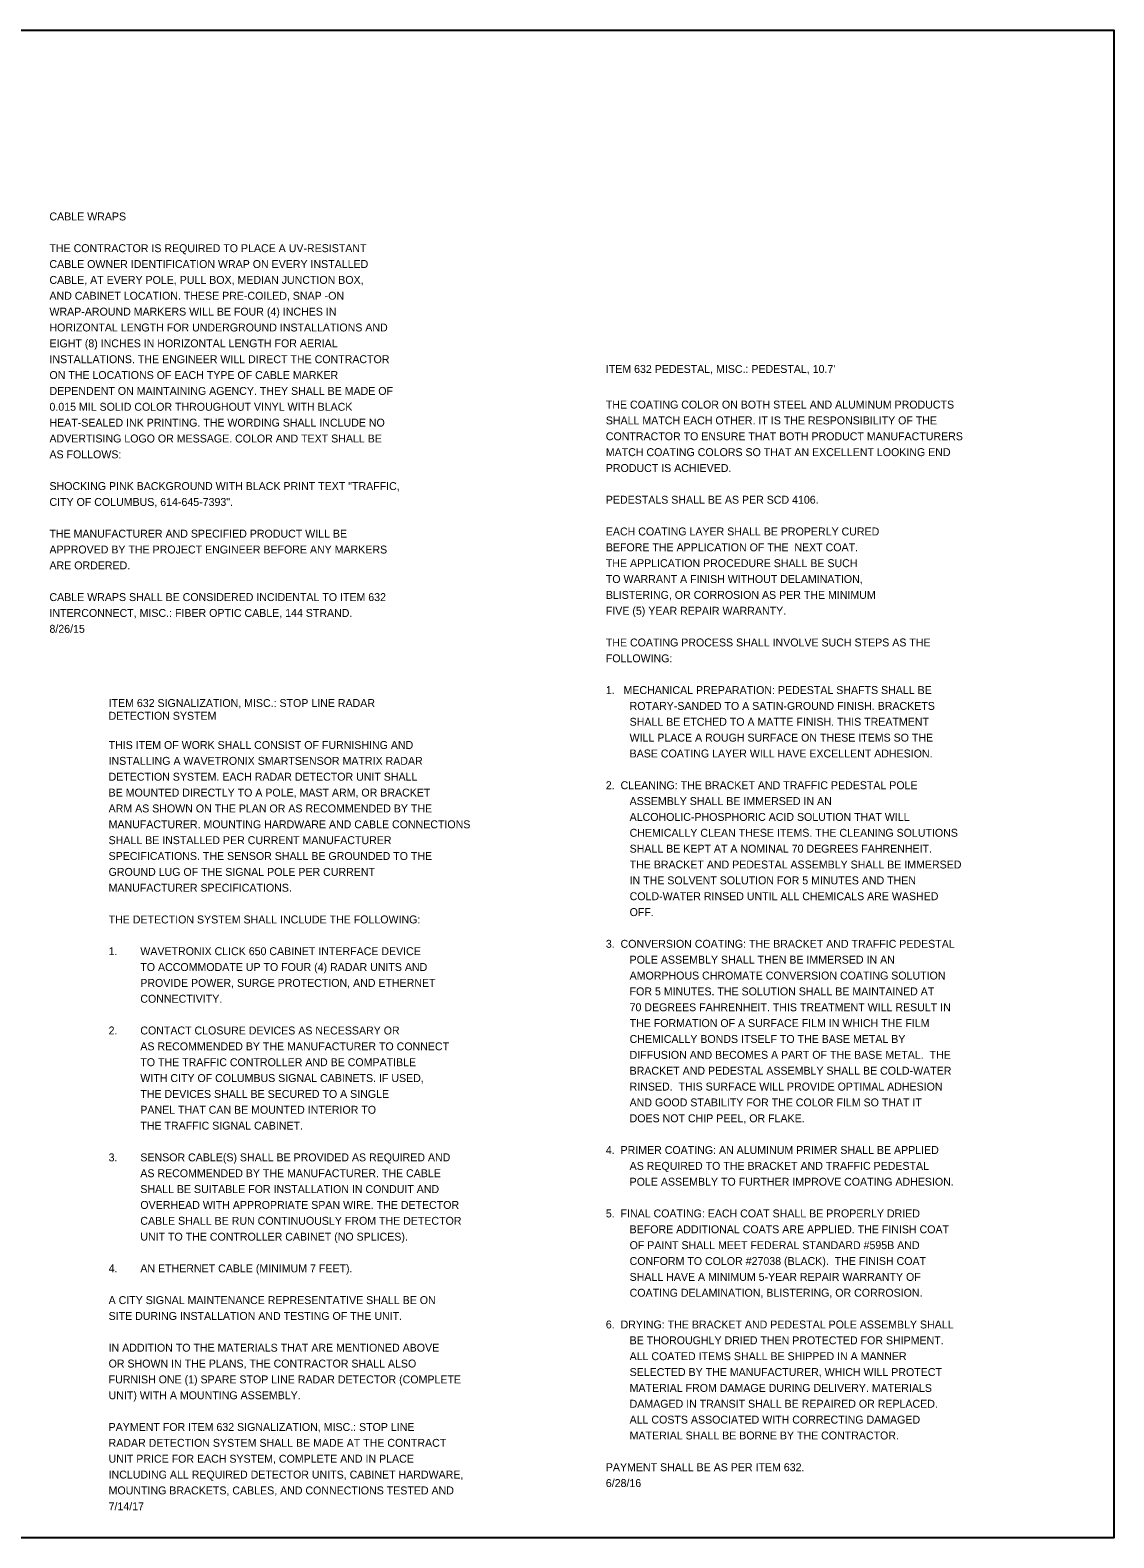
# Model space of a CAD drawing. Extents: x -41.3 to 53.7, y -40.1 to 14.5.
# Drawn here: x 12.93 to 32.05, y -40.09 to -13.47 of the extents above; entities that cross this region are included whole.
import ezdxf

# ---------------------------------------------------------------- set-up
doc = ezdxf.new("R2010")
doc.units = 0
doc.layers.add('SH_Data', color=7, linetype='Continuous')
doc.layers.add('SH_Text', color=7, linetype='Continuous')

msp = doc.modelspace()

# ---------------------------------------------------------------- linework, layer by layer
at = {"layer": 'SH_Text'}
msp.add_lwpolyline([(-41.349, -13.474), (32.055, -13.474), (32.055, -40.091), (-41.349, -40.091)], close=True, dxfattribs=at)

# ---------------------------------------------------------------- texts
at = {"layer": 'SH_Data'}
msp.add_text('CABLE WRAPS', height=0.14, dxfattribs=at).set_placement((13.266, -16.833))
for s, p in [("ITEM 632 PEDESTAL, MISC.: PEDESTAL, 10.7'", (23.087, -19.525)), ('ITEM 632 SIGNALIZATION, MISC.: STOP LINE RADAR ', (14.31, -25.423)), ('DETECTION SYSTEM', (14.31, -25.648))]:
    msp.add_text(s, height=0.14, rotation=360, dxfattribs=at).set_placement(p)
at = {"layer": 'SH_Text'}
for s, p in [('THE CONTRACTOR IS REQUIRED TO PLACE A UV-RESISTANT ', (13.266, -17.393)), ('CABLE OWNER IDENTIFICATION WRAP ON EVERY INSTALLED ', (13.266, -17.673)), ('CABLE, AT EVERY POLE, PULL BOX, MEDIAN JUNCTION BOX, ', (13.266, -17.953)), ('AND CABINET LOCATION. THESE PRE-COILED, SNAP -ON ', (13.266, -18.233)), ('WRAP-AROUND MARKERS WILL BE FOUR (4) INCHES IN ', (13.266, -18.513)), ('HORIZONTAL LENGTH FOR UNDERGROUND INSTALLATIONS AND ', (13.266, -18.793)), ('EIGHT (8) INCHES IN HORIZONTAL LENGTH FOR AERIAL ', (13.266, -19.073)), ('INSTALLATIONS. THE ENGINEER WILL DIRECT THE CONTRACTOR ', (13.266, -19.353)), ('ON THE LOCATIONS OF EACH TYPE OF CABLE MARKER ', (13.266, -19.633)), ('DEPENDENT ON MAINTAINING AGENCY. THEY SHALL BE MADE OF ', (13.266, -19.913)), ('0.015 MIL SOLID COLOR THROUGHOUT VINYL WITH BLACK ', (13.266, -20.193)), ('THE COATING COLOR ON BOTH STEEL AND ALUMINUM PRODUCTS ', (23.087, -20.154)), ('HEAT-SEALED INK PRINTING. THE WORDING SHALL INCLUDE NO ', (13.266, -20.473)), ('SHALL MATCH EACH OTHER. IT IS THE RESPONSIBILITY OF THE ', (23.087, -20.434)), ('ADVERTISING LOGO OR MESSAGE. COLOR AND TEXT SHALL BE ', (13.266, -20.753)), ('CONTRACTOR TO ENSURE THAT BOTH PRODUCT MANUFACTURERS ', (23.087, -20.714)), ('AS FOLLOWS: ', (13.266, -21.033)), ('MATCH COATING COLORS SO THAT AN EXCELLENT LOOKING END ', (23.087, -20.994)), ('PRODUCT IS ACHIEVED. ', (23.087, -21.274)), ('SHOCKING PINK BACKGROUND WITH BLACK PRINT TEXT "TRAFFIC, ', (13.266, -21.593)), ('CITY OF COLUMBUS, 614-645-7393". ', (13.266, -21.873)), ('PEDESTALS SHALL BE AS PER SCD 4106.  ', (23.087, -21.834)), ('THE MANUFACTURER AND SPECIFIED PRODUCT WILL BE ', (13.266, -22.433)), ('EACH COATING LAYER SHALL BE PROPERLY CURED', (23.087, -22.394)), ('APPROVED BY THE PROJECT ENGINEER BEFORE ANY MARKERS ', (13.266, -22.713)), ('BEFORE THE APPLICATION OF THE  NEXT COAT.', (23.087, -22.674)), ('ARE ORDERED.', (13.266, -22.993)), ('THE APPLICATION PROCEDURE SHALL BE SUCH', (23.087, -22.954)), ('TO WARRANT A FINISH WITHOUT DELAMINATION,', (23.087, -23.234)), ('CABLE WRAPS SHALL BE CONSIDERED INCIDENTAL TO ITEM 632 ', (13.266, -23.553)), ('BLISTERING, OR CORROSION AS PER THE MINIMUM', (23.087, -23.514)), ('FIVE (5) YEAR REPAIR WARRANTY. ', (23.087, -23.794)), ('INTERCONNECT, MISC.: FIBER OPTIC CABLE, 144 STRAND.', (13.266, -23.833)), ('8/26/15', (13.266, -24.113)), ('THE COATING PROCESS SHALL INVOLVE SUCH STEPS AS THE', (23.087, -24.354)), ('FOLLOWING:', (23.087, -24.634)), ('1.   MECHANICAL PREPARATION: PEDESTAL SHAFTS SHALL BE ', (23.087, -25.194)), ('ROTARY-SANDED TO A SATIN-GROUND FINISH. BRACKETS ', (23.507, -25.474)), ('SHALL BE ETCHED TO A MATTE FINISH. THIS TREATMENT ', (23.507, -25.754)), ('THIS ITEM OF WORK SHALL CONSIST OF FURNISHING AND ', (14.31, -26.164)), ('WILL PLACE A ROUGH SURFACE ON THESE ITEMS SO THE ', (23.507, -26.034)), ('INSTALLING A WAVETRONIX SMARTSENSOR MATRIX RADAR ', (14.31, -26.444)), ('BASE COATING LAYER WILL HAVE EXCELLENT ADHESION.', (23.507, -26.314)), ('DETECTION SYSTEM. EACH RADAR DETECTOR UNIT SHALL ', (14.31, -26.724)), ('BE MOUNTED DIRECTLY TO A POLE, MAST ARM, OR BRACKET ', (14.31, -27.004)), ('2.  CLEANING: THE BRACKET AND TRAFFIC PEDESTAL POLE ', (23.087, -26.874)), ('ARM AS SHOWN ON THE PLAN OR AS RECOMMENDED BY THE ', (14.31, -27.284)), ('ASSEMBLY SHALL BE IMMERSED IN AN ', (23.507, -27.154)), ('ALCOHOLIC-PHOSPHORIC ACID SOLUTION THAT WILL ', (23.507, -27.434)), ('MANUFACTURER. MOUNTING HARDWARE AND CABLE CONNECTIONS ', (14.31, -27.564)), ('CHEMICALLY CLEAN THESE ITEMS. THE CLEANING SOLUTIONS ', (23.507, -27.714)), ('SHALL BE INSTALLED PER CURRENT MANUFACTURER ', (14.31, -27.844)), ('SHALL BE KEPT AT A NOMINAL 70 DEGREES FAHRENHEIT.  ', (23.507, -27.994)), ('SPECIFICATIONS. THE SENSOR SHALL BE GROUNDED TO THE ', (14.31, -28.124)), ('THE BRACKET AND PEDESTAL ASSEMBLY SHALL BE IMMERSED ', (23.507, -28.274)), ('GROUND LUG OF THE SIGNAL POLE PER CURRENT ', (14.31, -28.404)), ('IN THE SOLVENT SOLUTION FOR 5 MINUTES AND THEN ', (23.507, -28.554)), ('MANUFACTURER SPECIFICATIONS.', (14.31, -28.684)), ('COLD-WATER RINSED UNTIL ALL CHEMICALS ARE WASHED ', (23.507, -28.834)), ('OFF.', (23.507, -29.114)), ('THE DETECTION SYSTEM SHALL INCLUDE THE FOLLOWING:', (14.31, -29.244)), ('3.  CONVERSION COATING: THE BRACKET AND TRAFFIC PEDESTAL ', (23.087, -29.674)), ('1.', (14.31, -29.804)), ('WAVETRONIX CLICK 650 CABINET INTERFACE DEVICE ', (14.87, -29.804)), ('TO ACCOMMODATE UP TO FOUR (4) RADAR UNITS AND ', (14.87, -30.084)), ('POLE ASSEMBLY SHALL THEN BE IMMERSED IN AN ', (23.507, -29.954)), ('PROVIDE POWER, SURGE PROTECTION, AND ETHERNET ', (14.87, -30.364)), ('AMORPHOUS CHROMATE CONVERSION COATING SOLUTION ', (23.507, -30.234)), ('CONNECTIVITY.', (14.87, -30.644)), ('FOR 5 MINUTES. THE SOLUTION SHALL BE MAINTAINED AT ', (23.507, -30.514)), ('70 DEGREES FAHRENHEIT. THIS TREATMENT WILL RESULT IN ', (23.507, -30.794)), ('2.', (14.31, -31.204)), ('CONTACT CLOSURE DEVICES AS NECESSARY OR ', (14.87, -31.204)), ('THE FORMATION OF A SURFACE FILM IN WHICH THE FILM ', (23.507, -31.074)), ('AS RECOMMENDED BY THE MANUFACTURER TO CONNECT ', (14.87, -31.484)), ('CHEMICALLY BONDS ITSELF TO THE BASE METAL BY ', (23.507, -31.354)), ('TO THE TRAFFIC CONTROLLER AND BE COMPATIBLE ', (14.87, -31.764)), ('DIFFUSION AND BECOMES A PART OF THE BASE METAL.  THE ', (23.507, -31.634)), ('WITH CITY OF COLUMBUS SIGNAL CABINETS. IF USED, ', (14.87, -32.044)), ('BRACKET AND PEDESTAL ASSEMBLY SHALL BE COLD-WATER ', (23.507, -31.914)), ('THE DEVICES SHALL BE SECURED TO A SINGLE ', (14.87, -32.324)), ('RINSED.  THIS SURFACE WILL PROVIDE OPTIMAL ADHESION ', (23.507, -32.194)), ('PANEL THAT CAN BE MOUNTED INTERIOR TO ', (14.87, -32.604)), ('AND GOOD STABILITY FOR THE COLOR FILM SO THAT IT ', (23.507, -32.474)), ('DOES NOT CHIP PEEL, OR FLAKE. ', (23.507, -32.754)), ('THE TRAFFIC SIGNAL CABINET.', (14.87, -32.884)), ('4.  PRIMER COATING: AN ALUMINUM PRIMER SHALL BE APPLIED ', (23.087, -33.314)), ('3.', (14.31, -33.444)), ('SENSOR CABLE(S) SHALL BE PROVIDED AS REQUIRED AND ', (14.87, -33.444)), ('AS REQUIRED TO THE BRACKET AND TRAFFIC PEDESTAL ', (23.507, -33.594)), ('AS RECOMMENDED BY THE MANUFACTURER. THE CABLE ', (14.87, -33.724)), ('POLE ASSEMBLY TO FURTHER IMPROVE COATING ADHESION.', (23.507, -33.874)), ('SHALL BE SUITABLE FOR INSTALLATION IN CONDUIT AND ', (14.87, -34.004)), ('OVERHEAD WITH APPROPRIATE SPAN WIRE. THE DETECTOR ', (14.87, -34.284)), ('5.  FINAL COATING: EACH COAT SHALL BE PROPERLY DRIED ', (23.087, -34.434)), ('CABLE SHALL BE RUN CONTINUOUSLY FROM THE DETECTOR ', (14.87, -34.564)), ('BEFORE ADDITIONAL COATS ARE APPLIED. THE FINISH COAT ', (23.507, -34.714)), ('UNIT TO THE CONTROLLER CABINET (NO SPLICES).', (14.87, -34.844)), ('OF PAINT SHALL MEET FEDERAL STANDARD #595B AND ', (23.507, -34.994)), ('CONFORM TO COLOR #27038 (BLACK).  THE FINISH COAT ', (23.507, -35.274)), ('4.', (14.31, -35.404)), ('AN ETHERNET CABLE (MINIMUM 7 FEET).', (14.87, -35.404)), ('SHALL HAVE A MINIMUM 5-YEAR REPAIR WARRANTY OF ', (23.507, -35.554)), ('A CITY SIGNAL MAINTENANCE REPRESENTATIVE SHALL BE ON ', (14.31, -35.964)), ('COATING DELAMINATION, BLISTERING, OR CORROSION.', (23.507, -35.834)), ('SITE DURING INSTALLATION AND TESTING OF THE UNIT.', (14.31, -36.244)), ('6.  DRYING: THE BRACKET AND PEDESTAL POLE ASSEMBLY SHALL ', (23.087, -36.394)), ('IN ADDITION TO THE MATERIALS THAT ARE MENTIONED ABOVE ', (14.31, -36.804)), ('BE THOROUGHLY DRIED THEN PROTECTED FOR SHIPMENT. ', (23.507, -36.674)), ('OR SHOWN IN THE PLANS, THE CONTRACTOR SHALL ALSO ', (14.31, -37.084)), ('ALL COATED ITEMS SHALL BE SHIPPED IN A MANNER ', (23.507, -36.954)), ('FURNISH ONE (1) SPARE STOP LINE RADAR DETECTOR (COMPLETE', (14.31, -37.364)), ('SELECTED BY THE MANUFACTURER, WHICH WILL PROTECT ', (23.507, -37.234)), ('UNIT) WITH A MOUNTING ASSEMBLY.', (14.31, -37.644)), ('MATERIAL FROM DAMAGE DURING DELIVERY. MATERIALS ', (23.507, -37.514)), ('DAMAGED IN TRANSIT SHALL BE REPAIRED OR REPLACED.  ', (23.507, -37.794)), ('PAYMENT FOR ITEM 632 SIGNALIZATION, MISC.: STOP LINE ', (14.31, -38.204)), ('ALL COSTS ASSOCIATED WITH CORRECTING DAMAGED ', (23.507, -38.074)), ('MATERIAL SHALL BE BORNE BY THE CONTRACTOR.', (23.507, -38.354)), ('RADAR DETECTION SYSTEM SHALL BE MADE AT THE CONTRACT ', (14.31, -38.484)), ('UNIT PRICE FOR EACH SYSTEM, COMPLETE AND IN PLACE ', (14.31, -38.764)), ('PAYMENT SHALL BE AS PER ITEM 632.', (23.087, -38.914)), ('INCLUDING ALL REQUIRED DETECTOR UNITS, CABINET HARDWARE, ', (14.31, -39.044)), ('6/28/16', (23.087, -39.194)), ('MOUNTING BRACKETS, CABLES, AND CONNECTIONS TESTED AND  ', (14.31, -39.324)), ('7/14/17', (14.31, -39.604))]:
    msp.add_text(s, height=0.14, rotation=360, dxfattribs=at).set_placement(p)

doc.saveas('drawing.dxf')
